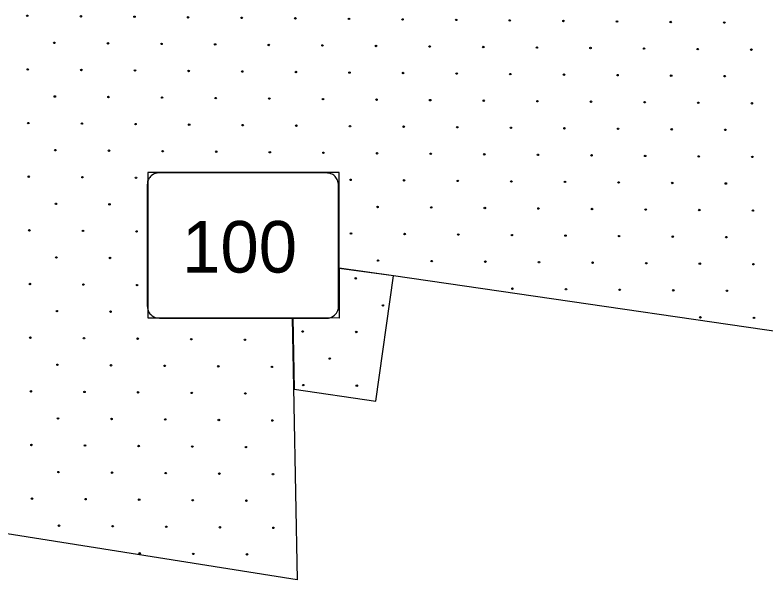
# Model space of a CAD drawing. Extents: x 1612280 to 1883141, y 560852 to 780851.
# Drawn here: x 1702292 to 1707678, y 625720 to 629769 of the extents above; entities that cross this region are included whole.
import ezdxf

# ---------------------------------------------------------------- set-up
doc = ezdxf.new("R2010")
doc.units = 0
for name, color, linetype in [('DESIGN - EROSION CONTROL - Devices', 7, 'Continuous'), ('DESIGN - ROW - Slope Lines', 7, 'Continuous'), ('DESIGN - SCRATCH - User 1', 7, 'Continuous')]:
    doc.layers.add(name, color=color, linetype=linetype)

msp = doc.modelspace()

# ---------------------------------------------------------------- linework, layer by layer
at = {"layer": 'DESIGN - EROSION CONTROL - Devices'}
for centre in [(1702379.8, 629764.1), (1702379.8, 629764.1), (1702764.4, 629760.4), (1702764.4, 629760.4), (1703148.9, 629756.7), (1703148.9, 629756.7), (1703533.5, 629752.9), (1703533.5, 629752.9), (1703918, 629749.2), (1703918, 629749.2), (1704302.6, 629745.5), (1704302.6, 629745.5), (1704687.2, 629741.7), (1704687.2, 629741.7), (1705071.7, 629738), (1705071.7, 629738), (1705456.3, 629734.3), (1705456.3, 629734.3), (1705840.8, 629730.5), (1705840.8, 629730.5), (1706225.4, 629726.8), (1706225.4, 629726.8), (1706609.9, 629723.1), (1706609.9, 629723.1), (1706994.5, 629719.3), (1706994.5, 629719.3), (1707379, 629715.6), (1707379, 629715.6), (1702574, 629570), (1702574, 629570), (1702958.5, 629566.3), (1702958.5, 629566.3), (1703343.1, 629562.5), (1703343.1, 629562.5), (1703727.6, 629558.8), (1703727.6, 629558.8), (1704112.2, 629555.1), (1704112.2, 629555.1), (1704496.7, 629551.3), (1704496.7, 629551.3), (1704881.3, 629547.6), (1704881.3, 629547.6), (1705265.9, 629543.9), (1705265.9, 629543.9), (1705650.4, 629540.1), (1705650.4, 629540.1), (1706035, 629536.4), (1706035, 629536.4), (1706419.5, 629532.7), (1706419.5, 629532.7), (1706804.1, 629528.9), (1706804.1, 629528.9), (1707188.6, 629525.2), (1707188.6, 629525.2), (1707573.2, 629521.5), (1707573.2, 629521.5), (1702383.6, 629379.6), (1702383.6, 629379.6), (1702768.1, 629375.9), (1702768.1, 629375.9), (1703152.7, 629372.1), (1703152.7, 629372.1), (1703537.2, 629368.4), (1703537.2, 629368.4), (1703921.8, 629364.7), (1703921.8, 629364.7), (1704306.3, 629360.9), (1704306.3, 629360.9), (1704690.9, 629357.2), (1704690.9, 629357.2), (1705075.4, 629353.5), (1705075.4, 629353.5), (1705460, 629349.7), (1705460, 629349.7), (1705844.5, 629346), (1705844.5, 629346), (1706229.1, 629342.3), (1706229.1, 629342.3), (1706613.7, 629338.5), (1706613.7, 629338.5), (1706998.2, 629334.8), (1706998.2, 629334.8), (1707382.8, 629331.1), (1707382.8, 629331.1), (1702577.7, 629185.4), (1702577.7, 629185.4), (1702962.3, 629181.7), (1702962.3, 629181.7), (1703346.8, 629178), (1703346.8, 629178), (1703731.4, 629174.2), (1703731.4, 629174.2), (1704115.9, 629170.5), (1704115.9, 629170.5), (1704500.5, 629166.8), (1704500.5, 629166.8), (1704885, 629163), (1704885, 629163), (1705269.6, 629159.3), (1705269.6, 629159.3), (1705654.1, 629155.6), (1705654.1, 629155.6), (1706038.7, 629151.8), (1706038.7, 629151.8), (1706423.2, 629148.1), (1706423.2, 629148.1), (1706807.8, 629144.4), (1706807.8, 629144.4), (1707192.3, 629140.6), (1707192.3, 629140.6), (1707576.9, 629136.9), (1707576.9, 629136.9), (1702387.3, 628995), (1702387.3, 628995), (1702771.9, 628991.3), (1702771.9, 628991.3), (1703156.4, 628987.6), (1703156.4, 628987.6), (1703541, 628983.8), (1703541, 628983.8), (1703925.5, 628980.1), (1703925.5, 628980.1), (1704310.1, 628976.4), (1704310.1, 628976.4), (1704694.6, 628972.6), (1704694.6, 628972.6), (1705079.2, 628968.9), (1705079.2, 628968.9), (1705463.7, 628965.2), (1705463.7, 628965.2), (1705848.3, 628961.4), (1705848.3, 628961.4), (1706232.8, 628957.7), (1706232.8, 628957.7), (1706617.4, 628954), (1706617.4, 628954), (1707001.9, 628950.2), (1707001.9, 628950.2), (1707386.5, 628946.5), (1707386.5, 628946.5), (1702581.4, 628800.9), (1702581.4, 628800.9), (1702966, 628797.2), (1702966, 628797.2), (1703350.6, 628793.4), (1703350.6, 628793.4), (1703735.1, 628789.7), (1703735.1, 628789.7), (1704119.7, 628786), (1704119.7, 628786), (1704504.2, 628782.2), (1704504.2, 628782.2), (1704888.8, 628778.5), (1704888.8, 628778.5), (1705273.3, 628774.8), (1705273.3, 628774.8), (1705657.9, 628771), (1705657.9, 628771), (1706042.4, 628767.3), (1706042.4, 628767.3), (1706427, 628763.6), (1706427, 628763.6), (1706811.5, 628759.8), (1706811.5, 628759.8), (1707196.1, 628756.1), (1707196.1, 628756.1), (1707580.6, 628752.4), (1707580.6, 628752.4), (1702391, 628610.5), (1702391, 628610.5), (1702775.6, 628606.8), (1702775.6, 628606.8), (1703160.1, 628603), (1703160.1, 628603), (1704698.4, 628588.1), (1704698.4, 628588.1), (1705082.9, 628584.4), (1705082.9, 628584.4), (1705467.5, 628580.6), (1705467.5, 628580.6), (1705852, 628576.9), (1705852, 628576.9), (1706236.6, 628573.2), (1706236.6, 628573.2), (1706621.1, 628569.4), (1706621.1, 628569.4), (1707005.7, 628565.7), (1707005.7, 628565.7), (1707390.2, 628562), (1707390.2, 628562), (1702585.2, 628416.3), (1702585.2, 628416.3), (1702969.7, 628412.6), (1702969.7, 628412.6), (1704892.5, 628393.9), (1704892.5, 628393.9), (1705277.1, 628390.2), (1705277.1, 628390.2), (1705661.6, 628386.5), (1705661.6, 628386.5), (1706046.2, 628382.7), (1706046.2, 628382.7), (1706430.7, 628379), (1706430.7, 628379), (1706815.3, 628375.3), (1706815.3, 628375.3), (1707199.8, 628371.5), (1707199.8, 628371.5), (1707584.4, 628367.8), (1707584.4, 628367.8), (1702394.8, 628225.9), (1702394.8, 628225.9), (1702779.3, 628222.2), (1702779.3, 628222.2), (1703163.9, 628218.5), (1703163.9, 628218.5), (1704702.1, 628203.5), (1704702.1, 628203.5), (1705086.6, 628199.8), (1705086.6, 628199.8), (1705471.2, 628196.1), (1705471.2, 628196.1), (1705855.7, 628192.3), (1705855.7, 628192.3), (1706240.3, 628188.6), (1706240.3, 628188.6), (1706624.9, 628184.9), (1706624.9, 628184.9), (1707009.4, 628181.1), (1707009.4, 628181.1), (1707394, 628177.4), (1707394, 628177.4), (1702588.9, 628031.8), (1702588.9, 628031.8), (1702973.5, 628028.1), (1702973.5, 628028.1), (1704896.2, 628009.4), (1704896.2, 628009.4), (1705280.8, 628005.7), (1705280.8, 628005.7), (1705665.3, 628001.9), (1705665.3, 628001.9), (1706049.9, 627998.2), (1706049.9, 627998.2), (1706434.4, 627994.5), (1706434.4, 627994.5), (1706819, 627990.7), (1706819, 627990.7), (1707203.6, 627987), (1707203.6, 627987), (1707588.1, 627983.3), (1707588.1, 627983.3), (1702398.5, 627841.4), (1702398.5, 627841.4), (1704736.1, 627882.1), (1704736.1, 627882.1), (1702783.1, 627837.6), (1702783.1, 627837.6), (1703167.6, 627833.9), (1703167.6, 627833.9), (1705859.5, 627807.8), (1705859.5, 627807.8), (1706244, 627804), (1706244, 627804), (1706628.6, 627800.3), (1706628.6, 627800.3), (1707013.1, 627796.6), (1707013.1, 627796.6), (1707397.7, 627792.8), (1707397.7, 627792.8), (1704930.3, 627688), (1704930.3, 627688), (1702592.6, 627647.2), (1702592.6, 627647.2), (1702977.2, 627643.5), (1702977.2, 627643.5), (1707207.3, 627602.4), (1707207.3, 627602.4), (1707591.8, 627598.7), (1707591.8, 627598.7), (1704355.3, 627501.3), (1704355.3, 627501.3), (1704739.9, 627497.6), (1704739.9, 627497.6), (1702402.2, 627456.8), (1702402.2, 627456.8), (1702786.8, 627453.1), (1702786.8, 627453.1), (1703171.3, 627449.4), (1703171.3, 627449.4), (1703555.9, 627445.6), (1703555.9, 627445.6), (1703940.5, 627441.9), (1703940.5, 627441.9), (1704549.4, 627307.1), (1704549.4, 627307.1), (1702596.4, 627262.7), (1702596.4, 627262.7), (1702980.9, 627259), (1702980.9, 627259), (1703365.5, 627255.2), (1703365.5, 627255.2), (1703750, 627251.5), (1703750, 627251.5), (1704134.6, 627247.7), (1704134.6, 627247.7), (1704359, 627116.7), (1704359, 627116.7), (1704743.6, 627113), (1704743.6, 627113), (1702406, 627072.3), (1702406, 627072.3), (1702790.5, 627068.5), (1702790.5, 627068.5), (1703175.1, 627064.8), (1703175.1, 627064.8), (1703559.6, 627061.1), (1703559.6, 627061.1), (1703944.2, 627057.3), (1703944.2, 627057.3), (1702600.1, 626878.1), (1702600.1, 626878.1), (1702984.7, 626874.4), (1702984.7, 626874.4), (1703369.2, 626870.7), (1703369.2, 626870.7), (1703753.8, 626866.9), (1703753.8, 626866.9), (1704138.3, 626863.2), (1704138.3, 626863.2), (1702409.7, 626687.7), (1702409.7, 626687.7), (1702794.3, 626684), (1702794.3, 626684), (1703178.8, 626680.3), (1703178.8, 626680.3), (1703563.4, 626676.5), (1703563.4, 626676.5), (1703947.9, 626672.8), (1703947.9, 626672.8), (1702603.8, 626493.6), (1702603.8, 626493.6), (1702988.4, 626489.8), (1702988.4, 626489.8), (1703373, 626486.1), (1703373, 626486.1), (1703757.5, 626482.4), (1703757.5, 626482.4), (1704142.1, 626478.6), (1704142.1, 626478.6), (1702413.4, 626303.2), (1702413.4, 626303.2), (1702798, 626299.4), (1702798, 626299.4), (1703182.5, 626295.7), (1703182.5, 626295.7), (1703567.1, 626292), (1703567.1, 626292), (1703951.7, 626288.2), (1703951.7, 626288.2), (1702607.6, 626109), (1702607.6, 626109), (1702992.1, 626105.3), (1702992.1, 626105.3), (1703376.7, 626101.6), (1703376.7, 626101.6), (1703761.2, 626097.8), (1703761.2, 626097.8), (1704145.8, 626094.1), (1704145.8, 626094.1), (1703186.3, 625911.1), (1703186.3, 625911.1), (1703570.8, 625907.4), (1703570.8, 625907.4), (1703955.4, 625903.7), (1703955.4, 625903.7)]:
    msp.add_circle(centre, 5.28, dxfattribs=at)
at = {"layer": 'DESIGN - ROW - Slope Lines'}
msp.add_line((1703239.7, 628537.2), (1703239.7, 627705.4), dxfattribs=at)
msp.add_line((1703239.7, 628537.2), (1703239.7, 627705.4), dxfattribs=at)
for points in [[(1704612.5, 628526.8), (1704612.4, 628534.6), (1704612.3, 628542.6), (1704611.2, 628557.2), (1704609.9, 628567.7), (1704608.1, 628578.5), (1704606.1, 628584.5), (1704602.9, 628591.1), (1704598.5, 628598.5), (1704593.1, 628605.9), (1704588.3, 628611.3), (1704582.5, 628616.9), (1704577.8, 628620.8), (1704571.3, 628625.3), (1704566.4, 628628.2), (1704558, 628632.2), (1704551.9, 628634.4), (1704544.7, 628635.7), (1704535.4, 628637.1), (1704527.3, 628638), (1704518.7, 628638.5), (1704506.3, 628638.6), (1704496.9, 628638), (1703339.6, 628638.7), (1703330.2, 628638.6), (1703320, 628637.9), (1703310.8, 628636.8), (1703301.7, 628635.1), (1703297.5, 628633.8), (1703290.2, 628630.8), (1703283.8, 628627.4), (1703278.6, 628624.2), (1703269.6, 628617.3), (1703263.5, 628611.5), (1703258.4, 628605.6), (1703254.5, 628600.3), (1703248.8, 628590.8), (1703245.4, 628583.4), (1703243.4, 628578.2), (1703242.7, 628574.5), (1703242.2, 628571.1), (1703241.4, 628563.9), (1703240.3, 628554.6), (1703239.8, 628546.7), (1703239.7, 628539.9), (1703239.7, 628522)], [(1704612.5, 628526.8), (1704612.4, 628534.6), (1704612.3, 628542.6), (1704611.2, 628557.2), (1704609.9, 628567.7), (1704608.1, 628578.5), (1704606.1, 628584.5), (1704602.9, 628591.1), (1704598.5, 628598.5), (1704593.1, 628605.9), (1704588.3, 628611.3), (1704582.5, 628616.9), (1704577.8, 628620.8), (1704571.3, 628625.3), (1704566.4, 628628.2), (1704558, 628632.2), (1704551.9, 628634.4), (1704544.7, 628635.7), (1704535.4, 628637.1), (1704527.3, 628638), (1704518.7, 628638.5), (1704506.3, 628638.6), (1704496.9, 628638), (1703339.6, 628638.7), (1703330.2, 628638.6), (1703320, 628637.9), (1703310.8, 628636.8), (1703301.7, 628635.1), (1703297.5, 628633.8), (1703290.2, 628630.8), (1703283.8, 628627.4), (1703278.6, 628624.2), (1703269.6, 628617.3), (1703263.5, 628611.5), (1703258.4, 628605.6), (1703254.5, 628600.3), (1703248.8, 628590.8), (1703245.4, 628583.4), (1703243.4, 628578.2), (1703242.7, 628574.5), (1703242.2, 628571.1), (1703241.4, 628563.9), (1703240.3, 628554.6), (1703239.8, 628546.7), (1703239.7, 628539.9), (1703239.7, 628522)], [(1704502.7, 627596.1), (1704523.3, 627596.4), (1704540.3, 627596.7), (1704550.6, 627599.1), (1704562.9, 627604), (1704574, 627610.3), (1704582.9, 627617.2), (1704591, 627625.2), (1704597.3, 627633.1), (1704603.3, 627642.9), (1704606.9, 627650.7), (1704609.4, 627657.8), (1704611, 627665.3), (1704611.8, 627673.5), (1704612.1, 627683.5), (1704612.5, 627706.8), (1704612.5, 628526.8)], [(1704502.7, 627596.1), (1704523.3, 627596.4), (1704540.3, 627596.7), (1704550.6, 627599.1), (1704562.9, 627604), (1704574, 627610.3), (1704582.9, 627617.2), (1704591, 627625.2), (1704597.3, 627633.1), (1704603.3, 627642.9), (1704606.9, 627650.7), (1704609.4, 627657.8), (1704611, 627665.3), (1704611.8, 627673.5), (1704612.1, 627683.5), (1704612.5, 627706.8), (1704612.5, 628526.8)], [(1703239.7, 627705.4), (1703239.8, 627696.4), (1703240.3, 627686.3), (1703241.1, 627676.9), (1703242.2, 627667.6), (1703243.6, 627658.4), (1703246.4, 627650.7), (1703249.8, 627643.6), (1703254.3, 627636.1), (1703259.7, 627628.8), (1703265.3, 627622.6), (1703272.6, 627616), (1703279.6, 627610.8), (1703287.5, 627606), (1703296.2, 627602), (1703305.1, 627599), (1703312.3, 627598), (1703327.3, 627596.8), (1703346.1, 627596.1), (1704502.7, 627596.1)], [(1703239.7, 627705.4), (1703239.8, 627696.4), (1703240.3, 627686.3), (1703241.1, 627676.9), (1703242.2, 627667.6), (1703243.6, 627658.4), (1703246.4, 627650.7), (1703249.8, 627643.6), (1703254.3, 627636.1), (1703259.7, 627628.8), (1703265.3, 627622.6), (1703272.6, 627616), (1703279.6, 627610.8), (1703287.5, 627606), (1703296.2, 627602), (1703305.1, 627599), (1703312.3, 627598), (1703327.3, 627596.8), (1703346.1, 627596.1), (1704502.7, 627596.1)]]:
    msp.add_lwpolyline(points, dxfattribs=at)
at = {"layer": 'DESIGN - SCRATCH - User 1'}
for points in [[(1703244.9, 628640.4), (1703244.1, 627598.1)], [(1703244.9, 628640.4), (1703244.1, 627598.1)], [(1704616.8, 628641.5), (1703244.9, 628640.4)], [(1704616.8, 628641.5), (1703244.9, 628640.4)], [(1704617.4, 627954.1), (1704616.8, 628641.5)], [(1704617.4, 627954.1), (1704616.8, 628641.5)], [(1705005.6, 627900.7), (1704617.4, 627954.1)], [(1705005.6, 627900.7), (1704617.4, 627954.1)], [(1705005.5, 627900.3), (1704617.4, 627953.6)], [(1704617.4, 627953.6), (1704617.6, 627597.7)], [(1705005.5, 627900.3), (1704617.4, 627953.6)], [(1704617.4, 627953.6), (1704617.6, 627597.7)], [(1704880, 627002.7), (1705005.5, 627900.3)], [(1704880, 627002.7), (1705005.5, 627900.3)], [(1708687, 627366.1), (1705005.6, 627900.7)], [(1708687, 627366.1), (1705005.6, 627900.7)], [(1704279.6, 627598.5), (1704316, 625720.3), (1700982.2, 626249.8), (1696792.9, 626947.1)], [(1704279.6, 627598.5), (1704316, 625720.3), (1700982.2, 626249.8), (1696792.9, 626947.1)], [(1703244.1, 627598.1), (1704279.6, 627598.5)], [(1703244.1, 627598.1), (1704279.6, 627598.5)], [(1704617.6, 627597.7), (1704285.5, 627598.7)], [(1704285.5, 627598.7), (1704295.1, 627087.5)], [(1704617.6, 627597.7), (1704285.5, 627598.7)], [(1704285.5, 627598.7), (1704295.1, 627087.5)], [(1704295.1, 627087.5), (1704880, 627002.7)], [(1704295.1, 627087.5), (1704880, 627002.7)]]:
    msp.add_lwpolyline(points, dxfattribs=at)

# ---------------------------------------------------------------- texts
at = {"layer": 'DESIGN - ROW - Slope Lines'}
msp.add_text('100', height=369.61, rotation=0.0011, dxfattribs=at).set_placement((1703490.4, 627923.5))
msp.add_text('100', height=369.61, rotation=0.0011, dxfattribs=at).set_placement((1703490.4, 627923.5))

doc.saveas('drawing.dxf')
